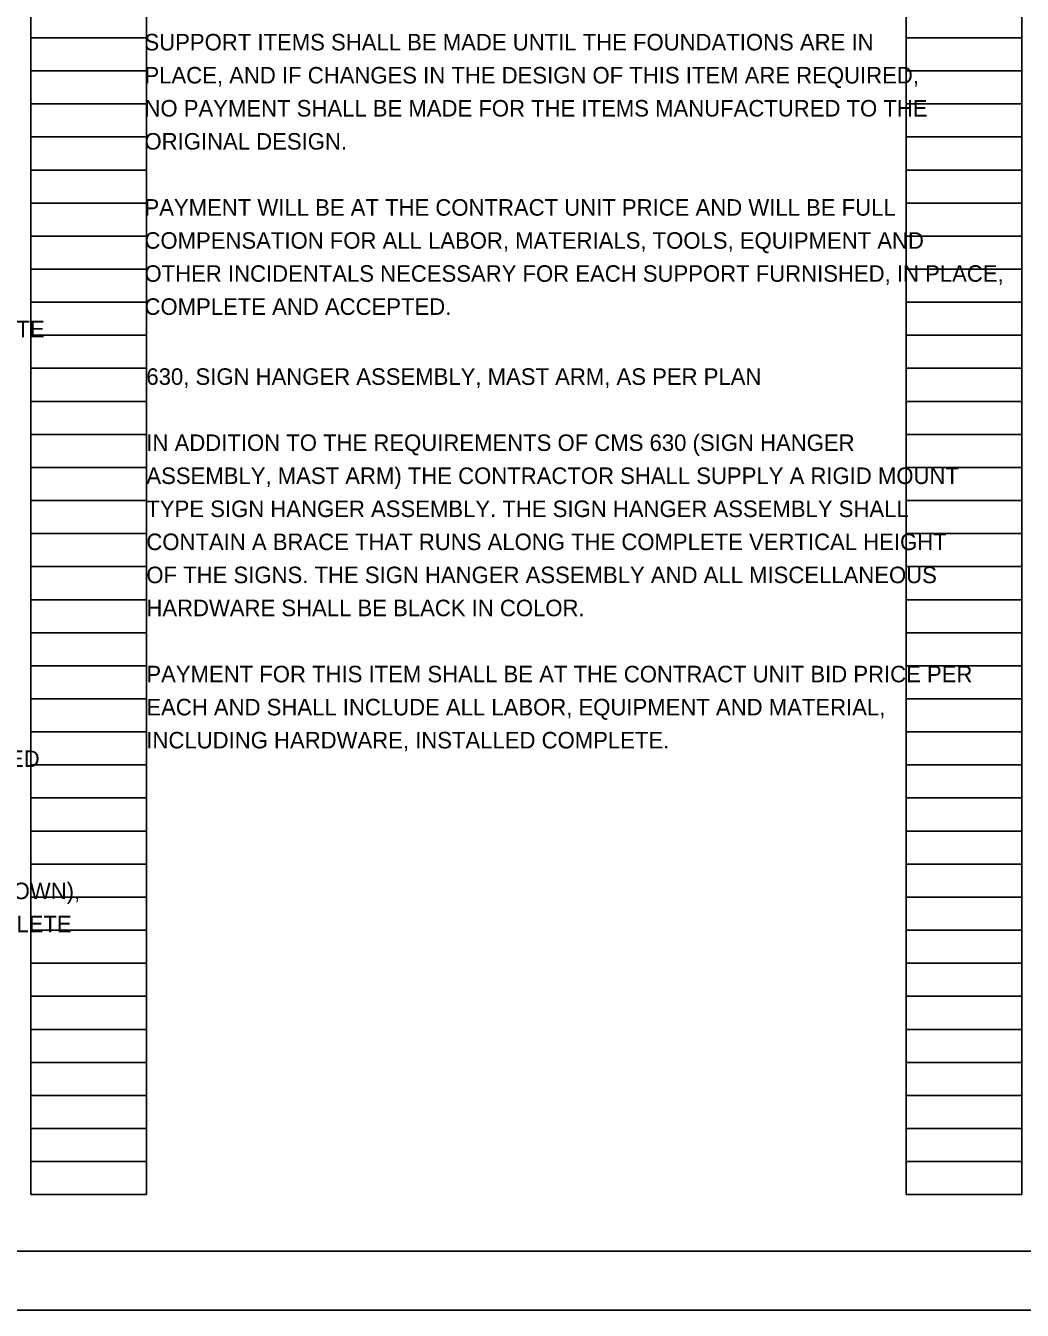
# Model space of a CAD drawing. Extents: x 0 to 34, y 0 to 22.
# Drawn here: x 16.22 to 24.66, y 0 to 10.88 of the extents above; entities that cross this region are included whole.
import ezdxf

# ---------------------------------------------------------------- set-up
doc = ezdxf.new("R2010")
doc.units = 0
for name, color, linetype in [('SH_Border', 7, 'Continuous'), ('SH_Cut_Line', 7, 'Continuous'), ('SH_Data', 7, 'Continuous'), ('SH_Text', 7, 'Continuous')]:
    doc.layers.add(name, color=color, linetype=linetype)

msp = doc.modelspace()

# ---------------------------------------------------------------- linework, layer by layer
at = {"layer": 'SH_Border'}
msp.add_lwpolyline([(1.5, 21.5), (33.5, 21.5), (33.5, 0.5), (1.5, 0.5)], close=True, dxfattribs=at)
at = {"layer": 'SH_Cut_Line'}
msp.add_lwpolyline([(0, 0), (34, 0), (34, 22), (0, 22)], close=True, dxfattribs=at)
at = {"layer": 'SH_Data'}
for p, q in [((16.26, 0.98), (16.26, 21.14)), ((17.24, 0.98), (17.24, 21.14)), ((23.68, 0.98), (23.68, 21.14)), ((24.66, 0.98), (24.66, 21.14)), ((16.26, 10.78), (17.24, 10.78)), ((23.68, 10.78), (24.66, 10.78)), ((16.26, 10.5), (17.24, 10.5)), ((23.68, 10.5), (24.66, 10.5)), ((16.26, 10.22), (17.24, 10.22)), ((23.68, 10.22), (24.66, 10.22)), ((16.26, 9.94), (17.24, 9.94)), ((23.68, 9.94), (24.66, 9.94)), ((16.26, 9.66), (17.24, 9.66)), ((23.68, 9.66), (24.66, 9.66)), ((16.26, 9.38), (17.24, 9.38)), ((23.68, 9.38), (24.66, 9.38)), ((16.26, 9.1), (17.24, 9.1)), ((23.68, 9.1), (24.66, 9.1)), ((16.26, 8.82), (17.24, 8.82)), ((23.68, 8.82), (24.66, 8.82)), ((16.26, 8.54), (17.24, 8.54)), ((23.68, 8.54), (24.66, 8.54)), ((16.26, 8.26), (17.24, 8.26)), ((23.68, 8.26), (24.66, 8.26)), ((16.26, 7.98), (17.24, 7.98)), ((23.68, 7.98), (24.66, 7.98)), ((16.26, 7.7), (17.24, 7.7)), ((23.68, 7.7), (24.66, 7.7)), ((16.26, 7.42), (17.24, 7.42)), ((23.68, 7.42), (24.66, 7.42)), ((16.26, 7.14), (17.24, 7.14)), ((23.68, 7.14), (24.66, 7.14)), ((16.26, 6.86), (17.24, 6.86)), ((23.68, 6.86), (24.66, 6.86)), ((16.26, 6.58), (17.24, 6.58)), ((23.68, 6.58), (24.66, 6.58)), ((16.26, 6.3), (17.24, 6.3)), ((23.68, 6.3), (24.66, 6.3)), ((16.26, 6.02), (17.24, 6.02)), ((23.68, 6.02), (24.66, 6.02)), ((16.26, 5.74), (17.24, 5.74)), ((23.68, 5.74), (24.66, 5.74)), ((16.26, 5.46), (17.24, 5.46)), ((23.68, 5.46), (24.66, 5.46)), ((16.26, 5.18), (17.24, 5.18)), ((23.68, 5.18), (24.66, 5.18)), ((16.26, 4.9), (17.24, 4.9)), ((23.68, 4.9), (24.66, 4.9)), ((16.26, 4.62), (17.24, 4.62)), ((23.68, 4.62), (24.66, 4.62)), ((16.26, 4.34), (17.24, 4.34)), ((23.68, 4.34), (24.66, 4.34)), ((16.26, 4.06), (17.24, 4.06)), ((23.68, 4.06), (24.66, 4.06)), ((16.26, 3.78), (17.24, 3.78)), ((23.68, 3.78), (24.66, 3.78)), ((16.26, 3.5), (17.24, 3.5)), ((23.68, 3.5), (24.66, 3.5)), ((16.26, 3.22), (17.24, 3.22)), ((23.68, 3.22), (24.66, 3.22)), ((16.26, 2.94), (17.24, 2.94)), ((23.68, 2.94), (24.66, 2.94)), ((16.26, 2.66), (17.24, 2.66)), ((23.68, 2.66), (24.66, 2.66)), ((16.26, 2.38), (17.24, 2.38)), ((23.68, 2.38), (24.66, 2.38)), ((16.26, 2.1), (17.24, 2.1)), ((23.68, 2.1), (24.66, 2.1)), ((16.26, 1.82), (17.24, 1.82)), ((23.68, 1.82), (24.66, 1.82)), ((16.26, 1.54), (17.24, 1.54)), ((23.68, 1.54), (24.66, 1.54)), ((16.26, 1.26), (17.24, 1.26)), ((23.68, 1.26), (24.66, 1.26)), ((16.26, 0.98), (17.24, 0.98)), ((23.68, 0.98), (24.66, 0.98))]:
    msp.add_line(p, q, dxfattribs=at)

# ---------------------------------------------------------------- texts
at = {"layer": 'SH_Text'}
for s, p in [('SUPPORT ITEMS SHALL BE MADE UNTIL THE FOUNDATIONS ARE IN ', (17.224, 10.673)), ('PLACE, AND IF CHANGES IN THE DESIGN OF THIS ITEM ARE REQUIRED, ', (17.224, 10.393)), ('NO PAYMENT SHALL BE MADE FOR THE ITEMS MANUFACTURED TO THE ', (17.224, 10.113)), ('ORIGINAL DESIGN.', (17.224, 9.833)), ('PAYMENT WILL BE AT THE CONTRACT UNIT PRICE AND WILL BE FULL ', (17.224, 9.273)), ('COMPENSATION FOR ALL LABOR, MATERIALS, TOOLS, EQUIPMENT AND ', (17.224, 8.993)), ('OTHER INCIDENTALS NECESSARY FOR EACH SUPPORT FURNISHED, IN PLACE, ', (17.224, 8.713)), ('COMPLETE AND ACCEPTED.', (17.224, 8.433)), ('3.  PIPE, SPACERS AND FITTINGS CONSTRUCTED OF POLYCARBONATE', (9.824, 8.243)), ('630, SIGN HANGER ASSEMBLY, MAST ARM, AS PER PLAN', (17.24, 7.84)), ('IN ADDITION TO THE REQUIREMENTS OF CMS 630 (SIGN HANGER ', (17.24, 7.28)), ('ASSEMBLY, MAST ARM) THE CONTRACTOR SHALL SUPPLY A RIGID MOUNT ', (17.24, 7)), ('TYPE SIGN HANGER ASSEMBLY. THE SIGN HANGER ASSEMBLY SHALL ', (17.24, 6.72)), ('CONTAIN A BRACE THAT RUNS ALONG THE COMPLETE VERTICAL HEIGHT ', (17.24, 6.44)), ('OF THE SIGNS. THE SIGN HANGER ASSEMBLY AND ALL MISCELLANEOUS ', (17.24, 6.16)), ('HARDWARE SHALL BE BLACK IN COLOR.', (17.24, 5.88)), ('PAYMENT FOR THIS ITEM SHALL BE AT THE CONTRACT UNIT BID PRICE PER ', (17.24, 5.32)), ('EACH AND SHALL INCLUDE ALL LABOR, EQUIPMENT AND MATERIAL, ', (17.24, 5.04)), ('INCLUDING HARDWARE, INSTALLED COMPLETE.', (17.24, 4.76)), ('     DESCRIPTION OF LAMP, AND DATE OF MANUFACTURE FOR ALL LED', (9.824, 4.603)), ('PAYMENT FOR ITEM 632 PEDESTRIAN SIGNAL HEAD (LED), (COUNTDOWN), ', (9.824, 3.483)), ('TYPE D2, AS PER PLAN SHALL BE MADE FOR THE NUMBER OF COMPLETE ', (9.824, 3.203))]:
    msp.add_text(s, height=0.14, dxfattribs=at).set_placement(p)

doc.saveas('drawing.dxf')
